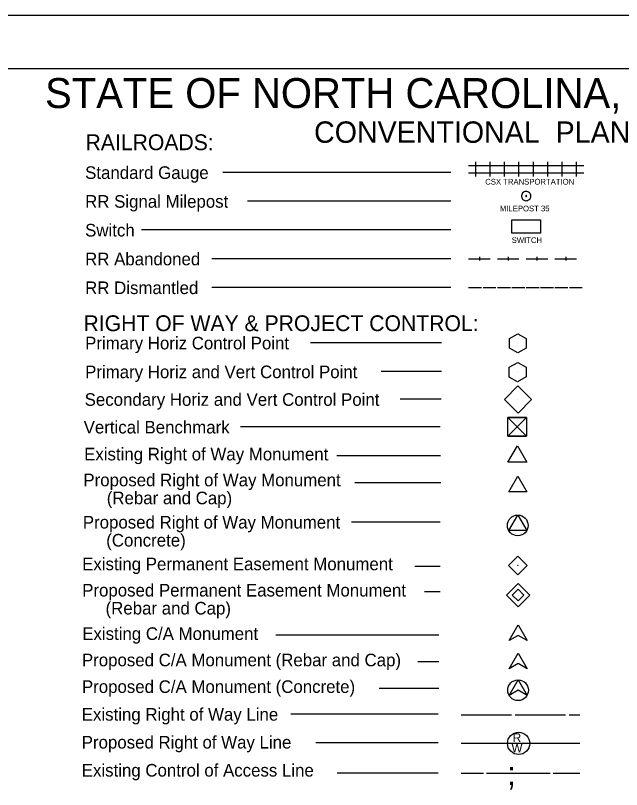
# Model space of a CAD drawing. Extents: x 1552903 to 1553044, y 811448 to 811540.
# Drawn here: x 1552937.98 to 1552973.4, y 811494.87 to 811540.09 of the extents above; entities that cross this region are included whole.
import ezdxf

# ---------------------------------------------------------------- set-up
doc = ezdxf.new("R2010")
doc.units = 0
for name, color, linetype in [('Exist DTM Breakline', 7, 'Continuous'), ('Exist Structure Major Bridge WW', 7, 'Continuous'), ('Exist Structure Minor Pipes CMP 15 Inch', 7, 'Continuous'), ('z - Construction', 7, 'Continuous')]:
    doc.layers.add(name, color=color, linetype=linetype)

msp = doc.modelspace()

# ---------------------------------------------------------------- linework, layer by layer
at = {"layer": 'Exist DTM Breakline'}
for p, q in [((1552964.461, 811531.321), (1552965.302, 811531.321)), ((1552964.882, 811530.69), (1552964.882, 811531.531)), ((1552965.302, 811531.321), (1552966.143, 811531.321)), ((1552965.722, 811530.69), (1552965.722, 811531.531)), ((1552966.143, 811531.321), (1552966.984, 811531.321)), ((1552966.563, 811530.69), (1552966.563, 811531.531)), ((1552966.984, 811531.321), (1552967.824, 811531.321)), ((1552967.404, 811530.69), (1552967.404, 811531.531)), ((1552967.824, 811531.321), (1552968.665, 811531.321)), ((1552968.245, 811530.69), (1552968.245, 811531.531)), ((1552968.665, 811531.321), (1552969.506, 811531.321)), ((1552969.086, 811530.69), (1552969.086, 811531.531)), ((1552969.506, 811531.321), (1552970.347, 811531.321)), ((1552969.926, 811530.69), (1552969.926, 811531.531)), ((1552970.347, 811531.321), (1552971.187, 811531.321)), ((1552970.767, 811530.69), (1552970.767, 811531.531)), ((1552963.419, 811530.92), (1552950.1, 811530.92)), ((1552964.461, 811530.9), (1552965.302, 811530.9)), ((1552965.302, 811530.9), (1552966.143, 811530.9)), ((1552966.143, 811530.9), (1552966.984, 811530.9)), ((1552966.984, 811530.9), (1552967.824, 811530.9)), ((1552967.824, 811530.9), (1552968.665, 811530.9)), ((1552968.665, 811530.9), (1552969.506, 811530.9)), ((1552969.506, 811530.9), (1552970.347, 811530.9)), ((1552970.347, 811530.9), (1552971.187, 811530.9)), ((1552963.419, 811529.239), (1552951.541, 811529.239)), ((1552963.419, 811527.557), (1552945.35, 811527.557)), ((1552963.419, 811525.876), (1552949.449, 811525.876)), ((1552964.461, 811525.876), (1552965.722, 811525.876)), ((1552965.092, 811525.981), (1552965.092, 811525.771)), ((1552966.143, 811525.876), (1552967.404, 811525.876)), ((1552966.773, 811525.981), (1552966.773, 811525.771)), ((1552967.824, 811525.876), (1552969.086, 811525.876)), ((1552968.455, 811525.981), (1552968.455, 811525.771)), ((1552969.506, 811525.876), (1552970.767, 811525.876)), ((1552970.136, 811525.981), (1552970.136, 811525.771)), ((1552963.419, 811524.194), (1552949.449, 811524.194)), ((1552963.419, 811524.194), (1552949.449, 811524.194)), ((1552964.461, 811524.194), (1552965.218, 811524.194)), ((1552965.302, 811524.194), (1552966.059, 811524.194)), ((1552966.143, 811524.194), (1552966.899, 811524.194)), ((1552966.984, 811524.194), (1552967.74, 811524.194)), ((1552967.824, 811524.194), (1552968.581, 811524.194)), ((1552968.665, 811524.194), (1552969.422, 811524.194)), ((1552969.506, 811524.194), (1552970.263, 811524.194)), ((1552970.347, 811524.194), (1552971.103, 811524.194)), ((1552962.88, 811520.966), (1552955.227, 811520.966)), ((1552967.331, 811520.935), (1552967.331, 811520.935)), ((1552962.88, 811519.285), (1552959.356, 811519.285)), ((1552967.33, 811519.256), (1552967.33, 811519.256)), ((1552962.854, 811517.67), (1552960.453, 811517.67)), ((1552967.342, 811517.652), (1552967.342, 811517.652)), ((1552962.796, 811516.054), (1552951.123, 811516.054)), ((1552967.299, 811516.055), (1552967.299, 811516.055)), ((1552962.822, 811514.374), (1552956.764, 811514.374)), ((1552962.831, 811512.795), (1552957.809, 811512.795)), ((1552967.33, 811512.575), (1552967.33, 811512.575)), ((1552962.789, 811510.49), (1552957.619, 811510.49)), ((1552967.332, 811510.299), (1552967.332, 811510.299)), ((1552962.795, 811507.91), (1552961.32, 811507.91)), ((1552967.338, 811507.965), (1552967.338, 811507.965)), ((1552962.795, 811506.428), (1552961.887, 811506.428)), ((1552966.826, 811503.577), (1552967.352, 811504.485)), ((1552967.352, 811504.485), (1552967.877, 811503.577)), ((1552962.712, 811503.888), (1552953.191, 811503.888)), ((1552967.352, 811503.88), (1552966.826, 811503.577)), ((1552967.877, 811503.577), (1552967.352, 811503.88)), ((1552966.824, 811501.928), (1552967.349, 811502.837)), ((1552967.349, 811502.837), (1552967.875, 811501.928)), ((1552962.72, 811502.329), (1552961.495, 811502.329)), ((1552967.349, 811502.231), (1552966.824, 811501.928)), ((1552967.875, 811501.928), (1552967.349, 811502.231)), ((1552966.824, 811500.372), (1552967.349, 811501.28)), ((1552967.349, 811501.28), (1552967.875, 811500.372)), ((1552962.72, 811500.773), (1552959.24, 811500.773)), ((1552967.349, 811500.675), (1552966.824, 811500.372)), ((1552967.875, 811500.372), (1552967.349, 811500.675)), ((1552962.683, 811499.278), (1552954.064, 811499.278)), ((1552964.031, 811499.23), (1552966.974, 811499.23)), ((1552967.184, 811499.23), (1552970.127, 811499.23)), ((1552970.337, 811499.23), (1552970.967, 811499.23)), ((1552962.683, 811497.597), (1552955.533, 811497.597)), ((1552964.031, 811497.586), (1552970.967, 811497.586)), ((1552962.683, 811495.821), (1552956.777, 811495.821)), ((1552964.031, 811495.821), (1552965.331, 811495.821)), ((1552965.499, 811495.821), (1552969.233, 811495.821)), ((1552969.401, 811495.821), (1552970.967, 811495.821))]:
    msp.add_line(p, q, dxfattribs=at)
for points in [[(1552968.099, 811529.538), (1552968.093, 811529.593), (1552968.077, 811529.647), (1552968.049, 811529.697), (1552968.011, 811529.735), (1552967.967, 811529.767), (1552967.918, 811529.795), (1552967.869, 811529.806), (1552967.809, 811529.811), (1552967.754, 811529.8), (1552967.705, 811529.784), (1552967.656, 811529.756), (1552967.618, 811529.718), (1552967.585, 811529.669), (1552967.563, 811529.62), (1552967.552, 811529.565), (1552967.552, 811529.511), (1552967.563, 811529.456), (1552967.585, 811529.407), (1552967.618, 811529.358), (1552967.656, 811529.32), (1552967.705, 811529.292), (1552967.754, 811529.276), (1552967.809, 811529.265), (1552967.869, 811529.27), (1552967.918, 811529.281), (1552967.967, 811529.309), (1552968.011, 811529.341), (1552968.049, 811529.38), (1552968.077, 811529.429), (1552968.093, 811529.483), (1552968.099, 811529.538)], [(1552967.836, 811529.571), (1552967.82, 811529.571), (1552967.804, 811529.56), (1552967.793, 811529.544), (1552967.798, 811529.527), (1552967.809, 811529.511), (1552967.825, 811529.505), (1552967.842, 811529.511), (1552967.853, 811529.522), (1552967.858, 811529.544), (1552967.853, 811529.56), (1552967.836, 811529.571)], [(1552967.331, 811520.376), (1552966.843, 811520.652), (1552966.843, 811521.212), (1552967.331, 811521.494), (1552967.818, 811521.218), (1552967.818, 811520.652), (1552967.331, 811520.376)], [(1552967.844, 811516.599), (1552966.753, 811515.509), (1552967.298, 811516.054), (1552967.844, 811515.509), (1552966.753, 811516.599)], [(1552967.298, 811516.054), (1552967.844, 811516.599), (1552966.753, 811516.599), (1552967.298, 811516.054)], [(1552967.298, 811516.054), (1552966.753, 811515.509), (1552967.844, 811515.509), (1552967.298, 811516.054)], [(1552966.762, 811513.999), (1552967.308, 811514.947), (1552967.854, 811513.999), (1552966.762, 811513.999)]]:
    msp.add_lwpolyline(points, dxfattribs=at)
for points in [[(1552966.984, 811528.143), (1552968.665, 811528.143), (1552968.665, 811527.378), (1552966.984, 811527.378)], [(1552966.84, 811519.54), (1552967.333, 811519.815), (1552967.826, 811519.544), (1552967.818, 811518.979), (1552967.325, 811518.692), (1552966.84, 811518.967)], [(1552966.55, 811517.655), (1552967.346, 811518.45), (1552968.142, 811517.654), (1552967.347, 811516.859)], [(1552966.753, 811516.599), (1552967.844, 811516.599), (1552967.844, 811515.509), (1552966.753, 811515.509)], [(1552966.805, 811512.272), (1552967.33, 811513.18), (1552967.856, 811512.272)], [(1552966.806, 811509.997), (1552967.332, 811510.905), (1552967.857, 811509.997)], [(1552966.792, 811507.965), (1552967.338, 811508.511), (1552967.884, 811507.965), (1552967.338, 811507.419)]]:
    msp.add_lwpolyline(points, close=True, dxfattribs=at)
for centre, radius in [((1552967.332, 811510.299), 0.605), ((1552967.338, 811507.965), 0.0106), ((1552967.349, 811500.675), 0.605), ((1552967.382, 811497.569), 0.652)]:
    msp.add_circle(centre, radius, dxfattribs=at)
at = {"layer": 'Exist Structure Major Bridge WW'}
msp.add_line((1553041.105, 811536.962), (1552905.688, 811536.962), dxfattribs=at)
at = {"layer": 'Exist Structure Minor Pipes CMP 15 Inch'}
msp.add_line((1552967.353, 811506.232), (1552967.353, 811506.232), dxfattribs=at)
for points in [[(1552967.353, 811506.909), (1552968.03, 811506.232), (1552967.353, 811505.555), (1552966.676, 811506.232)], [(1552967.353, 811506.571), (1552967.692, 811506.232), (1552967.353, 811505.894), (1552967.015, 811506.232)]]:
    msp.add_lwpolyline(points, close=True, dxfattribs=at)
at = {"layer": 'z - Construction'}
msp.add_line((1553044.23, 811540.087), (1552902.563, 811540.087), dxfattribs=at)

# ---------------------------------------------------------------- texts
at = {"layer": 'Exist DTM Breakline'}
for s, height, p in [('STATE OF NORTH CAROLINA, DIVISION OF HIGHWAYS', 1.75, (1552939.708, 811534.68)), ('CONVENTIONAL  PLAN SHEET SYMBOLS', 1.25, (1552955.429, 811532.649)), ('RAILROADS:', 0.9249, (1552942.073, 811532.219)), ('Standard Gauge', 0.73569, (1552942.05, 811530.54)), ('CSX TRANSPORTATION', 0.33631, (1552965.433, 811530.208)), ('RR Signal Milepost', 0.73569, (1552942.05, 811528.858)), ('MILEPOST 35', 0.33631, (1552966.29, 811528.646)), ('Switch', 0.7357, (1552942.05, 811527.177)), ('SWITCH', 0.3363, (1552966.979, 811526.796)), ('RR Abandoned', 0.73569, (1552942.05, 811525.495)), ('RR Dismantled', 0.73569, (1552942.05, 811523.814)), ('RIGHT OF WAY & PROJECT CONTROL:', 0.92486, (1552941.955, 811521.648)), ('Primary Horiz Control Point', 0.73569, (1552942.05, 811520.584)), ('Primary Horiz and Vert Control Point', 0.73569, (1552942.05, 811518.902)), ('Secondary Horiz and Vert Control Point', 0.73569, (1552942.024, 811517.287)), ('Vertical Benchmark', 0.73569, (1552941.966, 811515.671)), ('Existing Right of Way Monument', 0.73569, (1552941.992, 811514.098)), ('Proposed Right of Way Monument', 0.73569, (1552941.948, 811512.587)), ('     (Rebar and Cap)', 0.73569, (1552941.948, 811511.536)), ('Proposed Right of Way Monument', 0.73569, (1552941.917, 811510.119)), ('     (Concrete)', 0.73569, (1552941.917, 811509.068)), ('Existing Permanent Easement Monument', 0.73569, (1552941.876, 811507.682)), ('Proposed Permanent Easement Monument', 0.73569, (1552941.879, 811506.148)), ('     (Rebar and Cap)', 0.73569, (1552941.879, 811505.098)), ('Existing C/A Monument', 0.73569, (1552941.881, 811503.612)), ('Proposed C/A Monument (Rebar and Cap)', 0.73569, (1552941.864, 811502.073)), ('Proposed C/A Monument (Concrete)', 0.73569, (1552941.864, 811500.516)), ('Existing Right of Way Line', 0.73569, (1552941.853, 811498.896)), ('Proposed Right of Way Line', 0.73569, (1552941.853, 811497.267)), ('R', 0.511, (1552967.04, 811497.646)), ('W', 0.511, (1552966.967, 811497.044)), ('Existing Control of Access Line', 0.73569, (1552941.853, 811495.631)), (';', 1.387, (1552966.704, 811495.132))]:
    msp.add_text(s, height=height, dxfattribs=at).set_placement(p)

doc.saveas('drawing.dxf')
